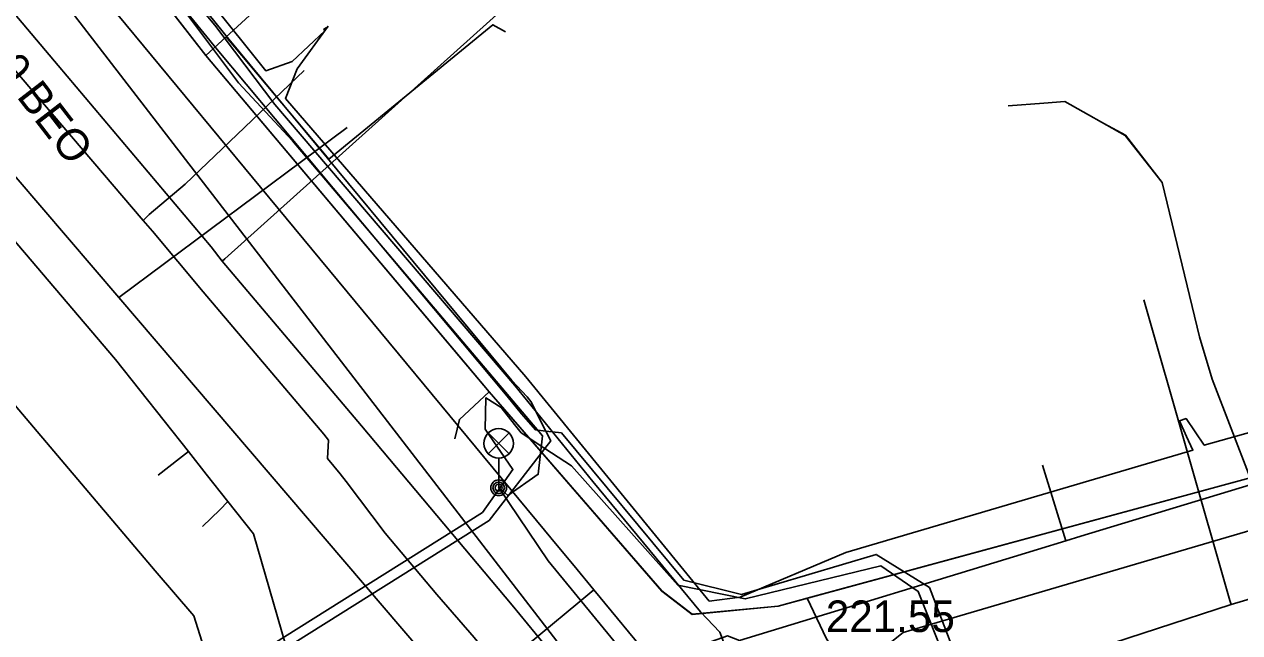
# Model space of a CAD drawing. Extents: x -595540 to -593988, y -1160850 to -1159202.
# Drawn here: x -595225.49 to -595194.66, y -1160562.74 to -1160547.33 of the extents above; entities that cross this region are included whole.
import ezdxf

# ---------------------------------------------------------------- set-up
doc = ezdxf.new("R2010")
doc.units = 0
for name, color, linetype in [('BVK-JEDNOTNA_trasa sítě', 7, 'Continuous'), ('BVK-KANALIZACE_ vyřazená trasa sítě', 7, 'Continuous'), ('BVK-KANALIZACE_popisy zrušené sítě', 7, 'Continuous'), ('BVK-VODOVOD_trasa sítě', 7, 'Continuous'), ('BVK-VODOVOD_trasa zrušené sítě', 7, 'Continuous'), ('CETIN_kabel podzemní', 7, 'Continuous'), ('DSP-SDEL-VODAFONE_kabel', 7, 'Continuous'), ('EON-NN_kabel', 7, 'Continuous'), ('EON-VN_kabel', 7, 'Continuous'), ('INNOGY-STL_trasa sítě', 7, 'Continuous'), ('JEDNOTNA_trasa neprovozované sítě', 7, 'Continuous'), ('TSB_kabel VO', 7, 'Continuous'), ('TSB_lampy VO', 7, 'Continuous')]:
    doc.layers.add(name, color=color, linetype=linetype)

msp = doc.modelspace()

# ---------------------------------------------------------------- linework, layer by layer
at = {"layer": 'BVK-JEDNOTNA_trasa sítě'}
msp.add_lwpolyline([(-595211.127, -1160568.232), (-595223.092, -1160554.252), (-595229.61, -1160546.64), (-595230.25, -1160545.89)], dxfattribs=at)
at = {"layer": 'BVK-KANALIZACE_ vyřazená trasa sítě'}
msp.add_lwpolyline([(-595208.649, -1160567.278), (-595220.855, -1160551.46), (-595226.408, -1160544.263), (-595228.241, -1160541.888), (-595228.485, -1160541.571), (-595230.959, -1160538.365), (-595232.578, -1160536.267), (-595233.912, -1160534.539)], dxfattribs=at)
at = {"layer": 'BVK-KANALIZACE_popisy zrušené sítě'}
msp.add_line((-595205.158, -1160561.928), (-595205.158, -1160561.928), dxfattribs=at)
at = {"layer": 'BVK-VODOVOD_trasa sítě'}
for points in [[(-595220.87, -1160558.73), (-595221.32, -1160558.15), (-595223.17, -1160555.82), (-595227.03, -1160551.3), (-595230.95, -1160546.74), (-595232.86, -1160544.52), (-595234.7, -1160542.18), (-595238.33, -1160537.35), (-595241.81, -1160532.49), (-595245.07, -1160527.57), (-595248.44, -1160522.6), (-595251.82, -1160517.68), (-595258.83, -1160508.01), (-595262.46, -1160503.34), (-595266.15, -1160498.56), (-595269.86, -1160493.93), (-595271.69, -1160491.54), (-595273.98, -1160488.26)], [(-595210.52, -1160565.18), (-595212.14, -1160563.23), (-595213.11, -1160562.05), (-595216.93, -1160557.5), (-595220.47, -1160553.33), (-595220.75, -1160552.97), (-595224.63, -1160548.37), (-595226.09, -1160546.63), (-595228.46, -1160543.8), (-595231.81, -1160539.79), (-595232.24, -1160539.27), (-595235.8, -1160534.87), (-595236, -1160534.62), (-595239.29, -1160530.1), (-595239.52, -1160529.78), (-595243.02, -1160525), (-595244.86, -1160522.46)], [(-595220.47, -1160553.33), (-595220.4, -1160553.27), (-595212.77, -1160546.41)], [(-595204.22, -1160565.07), (-595194.88, -1160562.03), (-595184.61, -1160558.98), (-595177.294, -1160556.814), (-595171.92, -1160555.22), (-595170.441, -1160554.743), (-595170.082, -1160554.627), (-595169.27, -1160554.364), (-595168.115, -1160553.991), (-595165.574, -1160553.171), (-595165.529, -1160553.156), (-595164.55, -1160552.84)], [(-595194.88, -1160562.03), (-595194.909, -1160561.93), (-595197.09, -1160554.313)], [(-595221.32, -1160558.15), (-595221.55, -1160558.33), (-595222.09, -1160558.75)], [(-595241.44, -1160578.07), (-595240.82, -1160577.91), (-595236.85, -1160576.86), (-595231.2, -1160575.37), (-595225.42, -1160573.84), (-595219.71, -1160572.34), (-595218.44, -1160572.01), (-595217.02, -1160569.41), (-595219.67, -1160560.24), (-595220.32, -1160559.42), (-595220.87, -1160558.73)], [(-595220.32, -1160559.42), (-595220.53, -1160559.63), (-595220.97, -1160560.05)]]:
    msp.add_lwpolyline(points, dxfattribs=at)
at = {"layer": 'BVK-VODOVOD_trasa zrušené sítě'}
for p, q in [((-595211.541, -1160561.053), (-595211.971, -1160560.534)), ((-595211.541, -1160561.053), (-595211.039, -1160561.659)), ((-595211.445, -1160561.996), (-595211.039, -1160561.659)), ((-595211.039, -1160561.659), (-595209, -1160564.12))]:
    msp.add_line(p, q, dxfattribs=at)
for points in [[(-595211.971, -1160560.534), (-595212.29, -1160560.149), (-595218.844, -1160552.24), (-595224.825, -1160545.022), (-595226.693, -1160542.768), (-595230.024, -1160538.368), (-595231.512, -1160536.403)], [(-595207.24, -1160566.05), (-595203.697, -1160563.135), (-595203.198, -1160562.743), (-595195.295, -1160560.421), (-595185.063, -1160557.415), (-595177.434, -1160555.174), (-595170.773, -1160553.217), (-595170.391, -1160553.105), (-595169.364, -1160552.803), (-595168.463, -1160552.538), (-595166.606, -1160551.993), (-595165.844, -1160551.769), (-595164.631, -1160551.413)], [(-595239.74, -1160571.98), (-595234.492, -1160570.398), (-595234.124, -1160570.296), (-595223.286, -1160567.267), (-595215.022, -1160564.958), (-595212.389, -1160562.777), (-595211.445, -1160561.996)]]:
    msp.add_lwpolyline(points, dxfattribs=at)
at = {"layer": 'CETIN_kabel podzemní'}
for points in [[(-595238.72, -1160541.65), (-595222.17, -1160561.18), (-595221.19, -1160562.32), (-595220.07, -1160565.85), (-595215.37, -1160571.44), (-595214.28, -1160572.44), (-595212.92, -1160574.05)], [(-595220.88, -1160548.12), (-595222.98, -1160545.42), (-595224.92, -1160543.19)], [(-595220.88, -1160548.12), (-595220.37, -1160547.65), (-595217.76, -1160550.75), (-595213.6, -1160547.34), (-595213.28, -1160547.52)], [(-595214.31, -1160555.91), (-595220.88, -1160548.12)], [(-595194.4, -1160558.82), (-595195.36, -1160556.32), (-595195.68, -1160555.25), (-595196.63, -1160551.34), (-595197.56, -1160550.14), (-595198.11, -1160549.84)], [(-595213.7, -1160556.64), (-595214.31, -1160555.91)], [(-595214.57, -1160557.83), (-595214.45, -1160557.34), (-595213.7, -1160556.64)], [(-595205.63, -1160561.87), (-595206.37, -1160562.07), (-595208.55, -1160562.28), (-595209.32, -1160561.69), (-595213.7, -1160556.64)], [(-595194.4, -1160558.82), (-595205.63, -1160561.87)], [(-595205.63, -1160561.87), (-595205.14, -1160562.9), (-595200.8, -1160569.21), (-595200.44, -1160570.07)]]:
    msp.add_lwpolyline(points, dxfattribs=at)
at = {"layer": 'DSP-SDEL-VODAFONE_kabel'}
for p, q in [((-595220.881, -1160548.117), (-595222.98, -1160545.424)), ((-595205.142, -1160562.899), (-595205.629, -1160561.872))]:
    msp.add_line(p, q, dxfattribs=at)
for points in [[(-595200.442, -1160570.066), (-595200.795, -1160569.212), (-595205.142, -1160562.899), (-595205.629, -1160561.872), (-595206.365, -1160562.072), (-595208.55, -1160562.279), (-595209.32, -1160561.685), (-595213.697, -1160556.641), (-595220.881, -1160548.117), (-595222.98, -1160545.424), (-595224.915, -1160543.187), (-595226.929, -1160540.86), (-595229.654, -1160537.145), (-595232.541, -1160533.598), (-595234.345, -1160530.922), (-595234.611, -1160530.558), (-595235.899, -1160528.761), (-595240.638, -1160522.188)], [(-595194.4, -1160558.824), (-595206.365, -1160562.072), (-595208.55, -1160562.279), (-595209.32, -1160561.685), (-595213.697, -1160556.641), (-595220.881, -1160548.117), (-595219.676, -1160547.015)], [(-595165.722, -1160548.991), (-595165.376, -1160550.172), (-595172.362, -1160552.221), (-595177.369, -1160553.689), (-595184.969, -1160556.037), (-595194.4, -1160558.824), (-595195.36, -1160556.318), (-595195.683, -1160555.252), (-595196.627, -1160551.336), (-595197.565, -1160550.143), (-595199.096, -1160549.285), (-595199.632, -1160549.329), (-595200.534, -1160549.397)]]:
    msp.add_lwpolyline(points, dxfattribs=at)
at = {"layer": 'EON-NN_kabel'}
for points in [[(-595195.801, -1160570.306), (-595196.043, -1160570.002), (-595197.511, -1160569.921), (-595199.621, -1160569.736), (-595199.732, -1160569.785), (-595201.011, -1160570.357), (-595202.135, -1160570.413), (-595207.31, -1160564.132), (-595207.848, -1160562.732), (-595208.337, -1160562.216), (-595211.069, -1160558.916), (-595213.043, -1160556.483), (-595219.135, -1160549.365), (-595220.655, -1160547.354), (-595224.182, -1160543.149), (-595224.672, -1160542.483), (-595228.688, -1160537.249), (-595232.048, -1160533.034), (-595233.905, -1160530.669), (-595234.938, -1160528.661), (-595235.696, -1160528.179), (-595239.874, -1160522.652)], [(-595217.776, -1160547.378), (-595217.813, -1160547.407), (-595217.888, -1160547.452), (-595217.865, -1160547.493), (-595218.695, -1160548.271), (-595219.361, -1160548.505), (-595222.252, -1160544.896)], [(-595185.817, -1160555.263), (-595195.56, -1160557.996), (-595196.022, -1160557.319), (-595196.185, -1160557.377), (-595196.007, -1160557.771), (-595195.847, -1160558.117), (-595204.654, -1160560.712), (-595207.328, -1160561.845), (-595208.114, -1160561.947), (-595212.762, -1160556.259), (-595218.858, -1160549.21), (-595218.564, -1160548.454), (-595217.776, -1160547.378)]]:
    msp.add_lwpolyline(points, dxfattribs=at)
at = {"layer": 'EON-VN_kabel'}
for points in [[(-595213.236, -1160556.754), (-595220.594, -1160547.971), (-595224.883, -1160542.711), (-595231.938, -1160533.557), (-595234.229, -1160530.496), (-595245.151, -1160515.279), (-595252.434, -1160505.242), (-595255.446, -1160501.602), (-595261.426, -1160493.221), (-595263.552, -1160489.92), (-595267.509, -1160484.697), (-595268.044, -1160482.73), (-595280.437, -1160465.869), (-595293.222, -1160447.996)], [(-595244.841, -1160515.037), (-595233.925, -1160530.241), (-595231.633, -1160533.296), (-595224.511, -1160542.396), (-595222.469, -1160545.009), (-595220.302, -1160547.704), (-595213.125, -1160556.353), (-595212.733, -1160556.765), (-595212.643, -1160556.885), (-595212.262, -1160557.634), (-595212.136, -1160557.881), (-595212.285, -1160558.074), (-595213.693, -1160559.9), (-595220.509, -1160564.172), (-595223.893, -1160566.164), (-595225.611, -1160567.303), (-595228.98, -1160568.661), (-595233.643, -1160569.981), (-595237.192, -1160571.072), (-595248.303, -1160574.298), (-595249.509, -1160574.72), (-595265.126, -1160578.838), (-595283.032, -1160583.766)], [(-595300.94, -1160588.38), (-595300.172, -1160587.93), (-595296.811, -1160587.149), (-595283.181, -1160583.393), (-595265.256, -1160578.465), (-595249.627, -1160574.335), (-595248.446, -1160573.918), (-595237.434, -1160570.399), (-595233.786, -1160569.642), (-595229.129, -1160568.288), (-595225.822, -1160566.967), (-595224.118, -1160565.745), (-595220.636, -1160563.949), (-595213.863, -1160559.698), (-595213.093, -1160558.609), (-595213.798, -1160557.589), (-595213.783, -1160556.794), (-595213.395, -1160557.035)], [(-595213.236, -1160556.754), (-595212.878, -1160557.198), (-595212.523, -1160557.604), (-595212.262, -1160557.634), (-595211.863, -1160557.679), (-595208.76, -1160561.41), (-595207.3, -1160561.78), (-595203.88, -1160560.76), (-595202.53, -1160561.6), (-595199.78, -1160568.77), (-595199.62, -1160569.59), (-595200.12, -1160571.6), (-595190.07, -1160583.7)], [(-595190.24, -1160583.86), (-595200.44, -1160571.7), (-595199.98, -1160568.81), (-595202.82, -1160561.7), (-595203.76, -1160561.05), (-595207.2, -1160561.89), (-595208.91, -1160561.54), (-595211.609, -1160558.519), (-595212.285, -1160558.074), (-595212.883, -1160557.679), (-595213.054, -1160557.473), (-595213.395, -1160557.035)]]:
    msp.add_lwpolyline(points, dxfattribs=at)
at = {"layer": 'INNOGY-STL_trasa sítě'}
for points in [[(-595245.641, -1160522.722), (-595244.446, -1160524.391), (-595243.702, -1160525.472), (-595241.563, -1160528.423), (-595241.184, -1160528.946), (-595239.934, -1160530.566), (-595237.988, -1160533.136), (-595236.901, -1160534.573), (-595235.649, -1160536.179), (-595233.747, -1160538.677), (-595232.502, -1160540.24), (-595228.314, -1160545.373), (-595227.838, -1160545.956), (-595226.558, -1160547.526), (-595222.467, -1160552.303), (-595222.233, -1160552.572), (-595220.953, -1160554.105), (-595217.888, -1160557.718)], [(-595222.467, -1160552.303), (-595222.318, -1160552.149), (-595221.405, -1160551.379), (-595218.391, -1160548.504)], [(-595210.23, -1160563.81), (-595209.35, -1160563.42), (-595207.65, -1160562.82), (-595207.35, -1160562.94), (-595207.15, -1160562.88), (-595199.79, -1160560.64), (-595199.07, -1160560.42), (-595198.69, -1160560.3), (-595191.97, -1160558.26), (-595191.01, -1160557.97), (-595190.77, -1160557.9), (-595186.7, -1160556.65), (-595185.74, -1160556.36), (-595185.12, -1160556.17), (-595180.52, -1160554.77), (-595179.85, -1160554.57), (-595179.25, -1160554.39), (-595173.61, -1160552.69), (-595173.42, -1160552.63), (-595172.18, -1160552.26), (-595167.51, -1160550.86), (-595166.46, -1160550.54), (-595166.13, -1160550.44)], [(-595217.888, -1160557.718), (-595217.769, -1160557.865), (-595217.797, -1160558.328), (-595217.477, -1160558.719)], [(-595199.07, -1160560.42), (-595199.66, -1160558.5)], [(-595213.02, -1160565.1), (-595213.79, -1160563.21), (-595214.08, -1160562.87), (-595215.02, -1160561.78), (-595216.33, -1160560.22), (-595217.32, -1160558.91), (-595217.477, -1160558.719)]]:
    msp.add_lwpolyline(points, dxfattribs=at)
at = {"layer": 'JEDNOTNA_trasa neprovozované sítě'}
msp.add_line((-595217.3, -1160549.94), (-595223.092, -1160554.252), dxfattribs=at)
at = {"layer": 'TSB_kabel VO'}
for points in [[(-595240.23, -1160522.28), (-595238.27, -1160525.07), (-595237.04, -1160526.74), (-595233.81, -1160531.11), (-595231.63, -1160534.18), (-595230.276, -1160535.952), (-595231.538, -1160536.914), (-595231.664, -1160537.108), (-595231.508, -1160537.029), (-595231.462, -1160537.006), (-595230.204, -1160536.048), (-595228.56, -1160538.27), (-595225.79, -1160541.74), (-595224.3, -1160543.51), (-595223.61, -1160544.4), (-595221.78, -1160546.51), (-595220.05, -1160548.81), (-595218.68, -1160550.28), (-595212.34, -1160557.76), (-595212.45, -1160558.73), (-595213.22, -1160559.27), (-595213.463, -1160559.054)], [(-595213.463, -1160559.054), (-595212.2, -1160560.92), (-595210.42, -1160563.09), (-595209.5, -1160563.75), (-595208.46, -1160564.08), (-595207.16, -1160564.01), (-595201.926, -1160570.563), (-595201.46, -1160569.794), (-595201.172, -1160569.358), (-595199.714, -1160568.78), (-595197.405, -1160568.135), (-595197.273, -1160568.505)]]:
    msp.add_lwpolyline(points, dxfattribs=at)
at = {"layer": 'TSB_lampy VO'}
for p, q in [((-595213.72, -1160558.212), (-595213.19, -1160557.682)), ((-595213.72, -1160557.682), (-595213.19, -1160558.212)), ((-595213.72, -1160558.212), (-595213.19, -1160557.682)), ((-595213.72, -1160557.682), (-595213.19, -1160558.212)), ((-595213.455, -1160558.322), (-595213.455, -1160559.072)), ((-595213.455, -1160558.322), (-595213.455, -1160559.072))]:
    msp.add_line(p, q, dxfattribs=at)
for centre, radius in [((-595213.455, -1160557.947), 0.375), ((-595213.455, -1160557.947), 0.375), ((-595213.455, -1160559.072), 0.2), ((-595213.455, -1160559.072), 0.2), ((-595213.455, -1160559.072), 0.145), ((-595213.455, -1160559.072), 0.145), ((-595213.455, -1160559.072), 0.0876), ((-595213.455, -1160559.072), 0.0876)]:
    msp.add_circle(centre, radius, dxfattribs=at)

# ---------------------------------------------------------------- texts
at = {"layer": 'BVK-KANALIZACE_popisy zrušené sítě'}
msp.add_text('DN 400 BEO', height=0.8, rotation=307.621, dxfattribs=at).set_placement((-595228.095, -1160546.052))
msp.add_text('221.55', height=0.8, dxfattribs=at).set_placement((-595205.158, -1160562.728))

doc.saveas('drawing.dxf')
